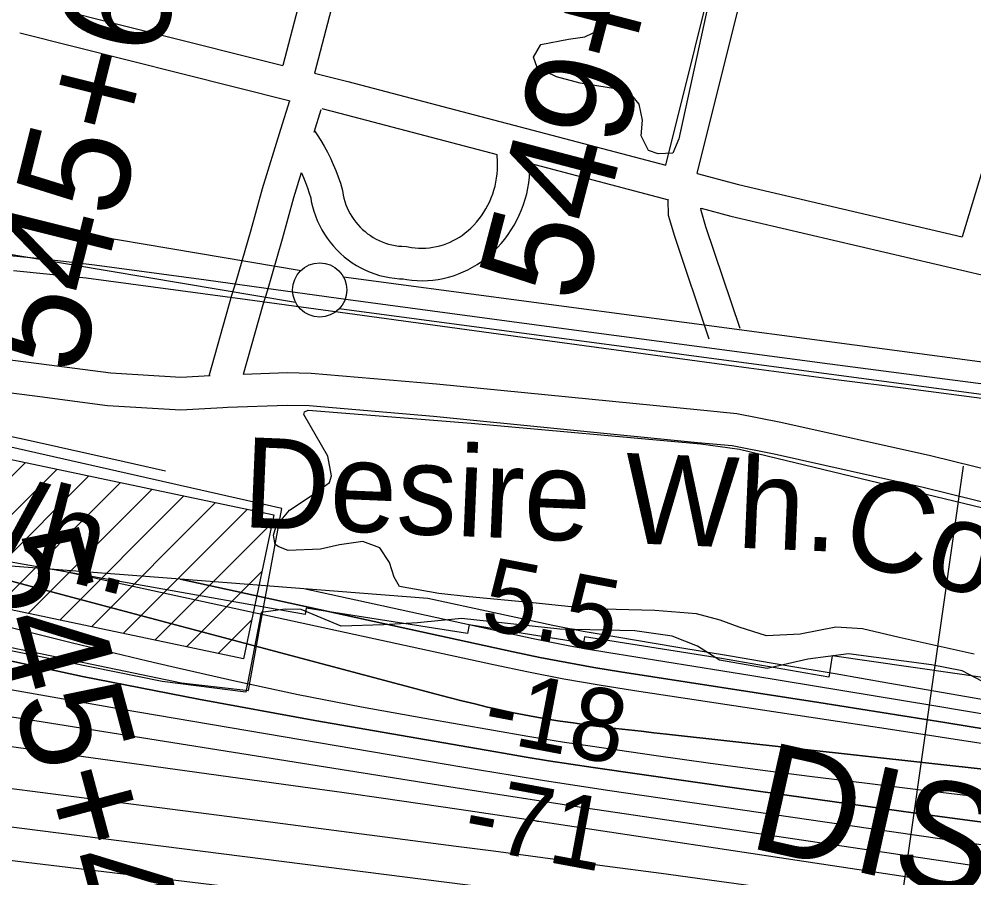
# Model space of a CAD drawing. Extents: x 3677843 to 3715951, y 511991 to 537744.
# Drawn here: x 3689113 to 3689993, y 533226 to 534017 of the extents above; entities that cross this region are included whole.
import ezdxf

# ---------------------------------------------------------------- set-up
doc = ezdxf.new("R2010")
doc.units = 0
for name, color, linetype in [('V-BLDG-IDEN', 7, 'Continuous'), ('V-BLDG-OTLN', 7, 'Continuous'), ('V-CHAN-DOCK', 7, 'Continuous'), ('V-RAIL-TRAK', 7, 'Continuous'), ('V-RIVR-EDGE', 7, 'Continuous'), ('V-RIVR-RANG', 7, 'Continuous'), ('V-ROAD-CNTR', 7, 'Continuous'), ('V-RRAP-RVMT', 7, 'Continuous'), ('V-RRAP-RVMT-IDEN', 7, 'Continuous'), ('V-SITE-VEGE', 7, 'Continuous'), ('V-SURV-IDEN', 7, 'Continuous'), ('V-SURV-LINE', 7, 'Continuous'), ('V-TOPO-DPTH', 7, 'Continuous'), ('V-TOPO-MAJR', 7, 'Continuous'), ('V-TOPO-MINR', 7, 'Continuous'), ('V-TOPO-WATR', 7, 'Continuous')]:
    doc.layers.add(name, color=color, linetype=linetype)

msp = doc.modelspace()

# ---------------------------------------------------------------- linework, layer by layer
at = {"layer": 'V-BLDG-OTLN'}
for p, q in [((3689004.53, 533494.26), (3689119.04, 533608.77)), ((3689033.73, 533488.11), (3689148.25, 533602.62)), ((3689062.94, 533481.95), (3689177.45, 533596.47)), ((3689092.14, 533475.8), (3689206.66, 533590.32)), ((3689121.35, 533469.65), (3689235.86, 533584.16)), ((3689150.55, 533463.5), (3689265.06, 533578.01)), ((3689179.76, 533457.35), (3689294.27, 533571.86)), ((3689208.96, 533451.2), (3689323.47, 533565.71)), ((3689238.16, 533445.05), (3689346.22, 533553.1)), ((3689267.37, 533438.9), (3689336.78, 533508.31)), ((3689296.57, 533432.74), (3689327.35, 533463.52))]:
    msp.add_line(p, q, dxfattribs=at)
msp.add_lwpolyline([(3688875.36, 533660.09), (3689347.79, 533560.59), (3689319.83, 533427.84), (3688828.91, 533531.25), (3688853.81, 533649.47), (3688872.31, 533645.58)], close=True, dxfattribs=at)
at = {"layer": 'V-CHAN-DOCK'}
for points in [[(3689334.93, 533456.71), (3689355.18, 533566.45), (3688859.4, 533678.6)], [(3689000.15, 533460.1), (3689143.16, 533430.64), (3689262.83, 533405.52), (3689324.55, 533398.53), (3689334.93, 533456.71)]]:
    msp.add_lwpolyline(points, dxfattribs=at)
at = {"layer": 'V-RAIL-TRAK'}
for points in [[(3687602.47, 533966), (3687663.49, 533948.65), (3687697.33, 533939.03), (3687747.16, 533923.87), (3687776.4, 533911.85), (3687837.18, 533889.99), (3687884.96, 533875.49), (3687949.07, 533861.83), (3688131.79, 533826.89), (3688277.03, 533798.37), (3688339.05, 533788.78), (3688360.19, 533784.9), (3688421.59, 533769.17), (3688503.39, 533755.01), (3688607.71, 533734.94), (3688724.29, 533714.31), (3688805.42, 533699.46), (3688857.27, 533686.36), (3688953.42, 533666.21), (3689033.23, 533647.95), (3689117.79, 533630.41), (3689209.86, 533609.54), (3689248.06, 533601.07)], [(3689094.69, 533800.45), (3689133.09, 533796.72), (3689182.48, 533791.04), (3689285.38, 533776.98), (3689327.58, 533771.22), (3689416.41, 533759.09), (3689624.28, 533731), (3689860.26, 533699.76), (3690088.7, 533669.81)], [(3691266.87, 533413.55), (3691105.3, 533454), (3691093.1, 533457.06), (3690844.48, 533519.01), (3690560.85, 533588.83), (3690529.95, 533596.06), (3690470.25, 533605.06), (3690353.64, 533620.35), (3690284.35, 533629.95), (3690166.11, 533645.88), (3689927.62, 533677.13), (3689868.63, 533684.77), (3689780.82, 533696.23), (3689583.93, 533723.06), (3689393.22, 533749.27), (3689323.58, 533758.65), (3689175.06, 533778.64), (3689107.85, 533785.51)]]:
    msp.add_lwpolyline(points, dxfattribs=at)
at = {"layer": 'V-RIVR-EDGE'}
msp.add_lwpolyline([(3690000.97, 533406.88), (3689982, 533416.73), (3689953.83, 533422.31), (3689877.27, 533432.31), (3689839.88, 533427.5), (3689802.48, 533419.01), (3689758.38, 533426.47), (3689738.2, 533439.39), (3689714.93, 533448.64), (3689680.63, 533453.62), (3689611.4, 533455.02), (3689520.74, 533465.05), (3689480.29, 533460.86), (3689449.04, 533459.1), (3689409.82, 533457.97), (3689373.09, 533473.38), (3689358.39, 533473.42), (3689336.32, 533470.41), (3689322.05, 533396.91), (3689244.87, 533406.91), (3689008.48, 533454.67)], dxfattribs=at)
at = {"layer": 'V-RIVR-RANG'}
msp.add_line((3689983.07, 533605.29), (3689864.68, 532773.68), dxfattribs=at)
at = {"layer": 'V-ROAD-CNTR'}
for points in [[(3689438.99, 534292.04), (3689356.17, 533974.83)], [(3689468.13, 534284.91), (3689385.27, 533967.54)], [(3689708.98, 533882.7), (3689789.7, 534206.15)], [(3689737.99, 533875.06), (3689818.84, 534199.02)], [(3690072.79, 534138.34), (3690034.22, 533989.01), (3689982.11, 533816.8)], [(3689114.62, 534035.4), (3689356.17, 533974.83)], [(3689113.67, 534004.72), (3689363.04, 533942.18)], [(3689385.27, 533967.54), (3689416.02, 533959.83), (3689708.98, 533882.7)], [(3689288.33, 533688.77), (3689309.21, 533762.95), (3689313.23, 533775.58), (3689326.97, 533823.07), (3689337.51, 533861.4), (3689354.35, 533916.14), (3689362.62, 533942.29)], [(3689384.93, 533913.32), (3689391.5, 533934.11)], [(3689392.05, 533934.91), (3689408.55, 533930.77), (3689553.81, 533892.53)], [(3689385.27, 533914.4), (3689387.79, 533910.77), (3689391.14, 533905.54), (3689394.3, 533900.19), (3689397.27, 533894.74), (3689400.05, 533889.19), (3689402.63, 533883.54), (3689405.01, 533877.8), (3689407.18, 533871.98), (3689409.15, 533866.09), (3689411.07, 533859.56), (3689411.82, 533855.29), (3689412.5, 533852.29), (3689413.34, 533849.32), (3689414.33, 533846.41), (3689415.48, 533843.55), (3689416.77, 533840.75), (3689418.21, 533838.03), (3689419.78, 533835.38), (3689421.5, 533832.82), (3689423.34, 533830.35), (3689425.31, 533827.99), (3689427.4, 533825.72), (3689429.61, 533823.57), (3689431.92, 533821.54), (3689434.33, 533819.63), (3689436.85, 533817.85), (3689439.45, 533816.21), (3689442.14, 533814.7), (3689444.9, 533813.34), (3689447.73, 533812.11), (3689450.62, 533811.04), (3689453.56, 533810.13), (3689456.55, 533809.36), (3689459.56, 533808.75), (3689462.61, 533808.31), (3689465.68, 533808.02), (3689470.14, 533807.83), (3689474.75, 533807.02), (3689478.02, 533806.62), (3689481.31, 533806.39), (3689484.61, 533806.32), (3689487.91, 533806.43), (3689491.2, 533806.7), (3689494.47, 533807.14), (3689497.71, 533807.75), (3689500.92, 533808.53), (3689504.08, 533809.46), (3689507.19, 533810.56), (3689510.25, 533811.82), (3689513.23, 533813.23), (3689516.14, 533814.8), (3689518.96, 533816.51), (3689521.69, 533818.36), (3689524.32, 533820.34), (3689526.85, 533822.47), (3689529.33, 533824.78), (3689532.03, 533827.5), (3689534.56, 533830.31), (3689536.97, 533833.23), (3689539.22, 533836.26), (3689541.34, 533839.39), (3689543.3, 533842.61), (3689545.11, 533845.93), (3689546.76, 533849.33), (3689548.25, 533852.8), (3689549.57, 533856.34), (3689550.73, 533859.93), (3689551.71, 533863.58), (3689552.53, 533867.28), (3689553.16, 533870.99), (3689553.63, 533874.74), (3689553.91, 533878.51), (3689554.02, 533882.29), (3689553.95, 533886.06), (3689553.55, 533892.18)], [(3689373.27, 533875.61), (3689375.12, 533871.56), (3689377.09, 533866.8), (3689378.89, 533861.98), (3689380.53, 533857.09), (3689381.81, 533852.73), (3689382.39, 533849.39), (3689383.42, 533844.86), (3689384.69, 533840.39), (3689386.19, 533835.99), (3689387.92, 533831.68), (3689389.87, 533827.46), (3689392.03, 533823.35), (3689394.41, 533819.35), (3689396.99, 533815.49), (3689399.77, 533811.77), (3689402.75, 533808.19), (3689405.9, 533804.78), (3689409.22, 533801.54), (3689412.72, 533798.48), (3689416.37, 533795.6), (3689420.16, 533792.91), (3689424.09, 533790.43), (3689428.14, 533788.15), (3689432.31, 533786.1), (3689436.57, 533784.26), (3689440.93, 533782.64), (3689445.37, 533781.26), (3689449.86, 533780.1), (3689454.42, 533779.19), (3689459.02, 533778.51), (3689463.65, 533778.08), (3689466.91, 533777.94), (3689470.32, 533777.34), (3689475.13, 533776.75), (3689479.95, 533776.41), (3689484.79, 533776.31), (3689489.63, 533776.47), (3689494.45, 533776.87), (3689499.24, 533777.51), (3689504, 533778.41), (3689508.71, 533779.54), (3689513.35, 533780.92), (3689517.91, 533782.53), (3689522.38, 533784.38), (3689526.76, 533786.44), (3689531.02, 533788.74), (3689535.16, 533791.24), (3689539.17, 533793.96), (3689543.03, 533796.88), (3689546.74, 533799.99), (3689550.21, 533803.23), (3689553.83, 533806.87), (3689557.3, 533810.72), (3689560.6, 533814.73), (3689563.7, 533818.89), (3689566.6, 533823.2), (3689569.3, 533827.64), (3689571.78, 533832.19), (3689574.05, 533836.85), (3689576.1, 533841.62), (3689577.91, 533846.48), (3689579.5, 533851.43), (3689580.86, 533856.44), (3689581.97, 533861.5), (3689582.85, 533866.62), (3689583.49, 533871.77), (3689583.88, 533876.94), (3689584.03, 533882.13), (3689583.98, 533884.58)], [(3689583.79, 533884.63), (3689711.67, 533850.97)], [(3689319.9, 533690.22), (3689337.95, 533754.34), (3689341.94, 533766.86), (3689355.84, 533814.92), (3689366.32, 533853.01), (3689373.38, 533875.97)], [(3689737.99, 533875.06), (3689776.07, 533865.03), (3689982.11, 533816.8)], [(3689749.12, 533722.57), (3689717.26, 533817.1), (3689711.68, 533836.29), (3689711.19, 533851.09)], [(3689777.55, 533732.15), (3689745.89, 533826.08), (3689741.54, 533841.05), (3689741.47, 533843.12)], [(3689741.64, 533843.08), (3689768.83, 533835.92), (3690100.22, 533758.34), (3690612.35, 533625.64), (3690894.5, 533559.6), (3691159.97, 533495.29), (3691208.29, 533482.58)], [(3688471.3, 533802.39), (3688711.98, 533762.57), (3688967.48, 533722.91), (3689042.25, 533711.43), (3689131.36, 533700.08), (3689197.66, 533691.28), (3689262.29, 533687.26), (3689289.14, 533688.82)], [(3689319.56, 533690.21), (3689360.12, 533691.6), (3689382.12, 533691.11), (3689497.8, 533681.31), (3689741.06, 533657.16), (3689774.46, 533654.01), (3689814.93, 533646.05), (3689953.05, 533615.35), (3690239.69, 533544.65)], [(3689038.08, 533681.72), (3689127.49, 533670.33), (3689194.75, 533661.4), (3689262.23, 533657.2), (3689300.74, 533659.45), (3689305.12, 533659.7), (3689360.3, 533661.59), (3689380.51, 533661.14), (3689495.05, 533651.43), (3689738.17, 533627.3), (3689770.15, 533624.29), (3689808.78, 533616.69), (3689946.2, 533586.14), (3690232.6, 533515.5)]]:
    msp.add_lwpolyline(points, dxfattribs=at)
at = {"layer": 'V-RRAP-RVMT'}
for points in [[(3689633.24, 533442.27), (3689527.85, 533459.14), (3689526.41, 533451.28), (3689377.6, 533474.35), (3689376.67, 533468.5), (3689094.94, 533518.68), (3689100.33, 533550.74), (3688954.27, 533578.27), (3688957.13, 533598.79), (3688817.32, 533626.57), (3688817.78, 533630.14), (3688670.66, 533660.32), (3688670.54, 533659.68), (3688553.23, 533683.31), (3688528.78, 533553.69)], [(3690009.36, 533409.37), (3689862.36, 533430.69), (3689859.34, 533410.9), (3689760.48, 533427.97), (3689760.51, 533428.16), (3689634.21, 533447.97), (3689633.24, 533442.27)]]:
    msp.add_lwpolyline(points, dxfattribs=at)
at = {"layer": 'V-SITE-VEGE'}
msp.add_lwpolyline([(3689759.98, 534085.99), (3689720.99, 533906.95), (3689715.68, 533893.99), (3689702.1, 533893.18), (3689693.24, 533896.49), (3689686.31, 533910.01), (3689687.53, 533924.28), (3689684.66, 533939.2), (3689677.79, 533947.28), (3689662.79, 533953.25), (3689630.13, 533958.36), (3689608.34, 533964.26), (3689590.59, 533972.92), (3689587.1, 533982.39), (3689593.78, 533994.01), (3689619.54, 533999.02), (3689634.46, 534001.2), (3689647.99, 534007.45), (3689662.67, 534034.09), (3689675.08, 534085.16), (3689677.66, 534098.09), (3689691.2, 534103.66), (3689723.85, 534098.54)], close=True, dxfattribs=at)
msp.add_lwpolyline([(3689993.13, 533431.98), (3689924.06, 533447.51), (3689890.21, 533455.29), (3689865.87, 533457.07), (3689832.83, 533450.67), (3689801.76, 533449.01), (3689776.69, 533456.87), (3689759.06, 533463.45), (3689737.38, 533469.32), (3689698.84, 533472.31), (3689639.38, 533473.75), (3689586.63, 533479.31), (3689527.79, 533484.82), (3689500.06, 533487.92), (3689463.52, 533494.32), (3689458.7, 533503.05), (3689454.52, 533516.52), (3689445.6, 533529.95), (3689430, 533535.87), (3689408.41, 533532.96), (3689390.89, 533528.73), (3689361.17, 533527.76), (3689352.36, 533531.05), (3689348.96, 533533.05), (3689347.52, 533541.81), (3689350.15, 533549.95), (3689362.16, 533564.93), (3689382.3, 533577.96), (3689399.07, 533590.29), (3689401.03, 533596.39), (3689397.48, 533614.59), (3689375.48, 533652.89), (3689376.13, 533655.6), (3689379.49, 533656.98), (3689529.59, 533644.95), (3689741.24, 533626.09), (3689777.1, 533621.04), (3690121.12, 533537.96)], dxfattribs=at)
at = {"layer": 'V-SURV-LINE'}
for points in [[(3689059.73, 533838.43), (3689372.93, 533785.88)], [(3689367.98, 533756.29), (3689056.89, 533808.48)], [(3689411.94, 533780.01), (3690353.79, 533654.5)], [(3690349.84, 533624.76), (3689407.99, 533750.27)]]:
    msp.add_lwpolyline(points, dxfattribs=at)
msp.add_circle((3689390.15, 533767.78), 25, dxfattribs=at)
at = {"layer": 'V-TOPO-DPTH'}
for points in [[(3689032.99, 533518.64), (3689497.32, 533395.2), (3689509.17, 533392.11), (3689521.05, 533389.09), (3689532.95, 533386.17), (3689544.86, 533383.33), (3689549.4, 533382.27), (3689559.08, 533380.1), (3689568.78, 533378.04), (3689578.52, 533376.15), (3689588.27, 533374.37), (3689604.07, 533371.63), (3689605.95, 533371.32), (3689607.82, 533371.01), (3689609.7, 533370.72), (3689611.58, 533370.44), (3689623.8, 533368.68), (3689631.79, 533367.56), (3689639.79, 533366.48), (3689647.79, 533365.47), (3689655.81, 533364.51), (3689663.07, 533363.66), (3689674.72, 533362.32), (3689686.38, 533360.99), (3689698.03, 533359.67), (3689709.69, 533358.37), (3690070.87, 533318.34)], [(3693858.12, 532595.84), (3691015.63, 533179.63), (3690973.58, 533188.25), (3690931.52, 533196.84), (3690889.46, 533205.39), (3690847.39, 533213.92), (3690821.55, 533219.14), (3690792.38, 533224.93), (3690763.19, 533230.58), (3690733.95, 533236.01), (3690704.68, 533241.29), (3690314.1, 533310.37), (3690198.23, 533330.48), (3690082.29, 533350.11), (3689966.23, 533369.01), (3689850.08, 533387.43), (3689667.42, 533415.8), (3689642.59, 533419.89), (3689617.81, 533424.28), (3689593.12, 533429.11), (3689568.48, 533434.24), (3689261.44, 533501.09), (3689032.99, 533518.64)], [(3689032.99, 533518.64), (3689497.32, 533395.2), (3689509.17, 533392.11), (3689521.05, 533389.09), (3689532.95, 533386.17), (3689544.86, 533383.33), (3689549.4, 533382.27), (3689559.08, 533380.1), (3689568.78, 533378.04), (3689578.52, 533376.15), (3689588.27, 533374.37), (3689604.07, 533371.63), (3689605.95, 533371.32), (3689607.82, 533371.01), (3689609.7, 533370.72), (3689611.58, 533370.44), (3689623.8, 533368.68), (3689631.79, 533367.56), (3689639.79, 533366.48), (3689647.79, 533365.47), (3689655.81, 533364.51), (3689663.07, 533363.66), (3689674.72, 533362.32), (3689686.38, 533360.99), (3689698.03, 533359.67), (3689709.69, 533358.37), (3690070.87, 533318.34)], [(3694353.57, 532541.82), (3690852.21, 533240.67), (3690838.27, 533243.43), (3690824.32, 533246.16), (3690810.37, 533248.86), (3690796.41, 533251.52), (3690782.44, 533254.13), (3690768.46, 533256.7), (3690754.47, 533259.21), (3690740.48, 533261.68), (3689913.5, 533405.47), (3689865.19, 533413.82), (3689816.87, 533422.09), (3689768.53, 533430.26), (3689720.19, 533438.36), (3689642.09, 533451.36), (3689632.8, 533452.97), (3689623.51, 533454.68), (3689614.26, 533456.53), (3689605.02, 533458.47), (3689489.88, 533483.54), (3689261.44, 533501.09)], [(3689261.44, 533501.09), (3689568.48, 533434.24), (3689593.12, 533429.11), (3689617.81, 533424.28), (3689642.59, 533419.89), (3689667.42, 533415.8), (3689850.08, 533387.43), (3689966.23, 533369.01), (3690082.29, 533350.11), (3690198.23, 533330.48), (3690314.1, 533310.37), (3690704.68, 533241.29), (3690733.95, 533236.01), (3690763.19, 533230.58), (3690792.38, 533224.93), (3690821.55, 533219.14), (3690847.39, 533213.92), (3690889.46, 533205.39), (3690931.52, 533196.84), (3690973.58, 533188.25), (3691015.63, 533179.63), (3693858.12, 532595.84)], [(3690021.85, 533297.45), (3689946.55, 533306.48), (3689892.08, 533313.05), (3689844.04, 533319.01), (3689796.04, 533325.2), (3689748.07, 533331.72), (3689700.14, 533338.47), (3689626.89, 533349.04), (3689615.61, 533350.72), (3689604.34, 533352.46), (3689593.09, 533354.3), (3689581.84, 533356.2), (3689487.05, 533372.64), (3689428.52, 533383.33), (3689370.14, 533394.72), (3689311.97, 533407.17), (3689253.94, 533420.31), (3689231.43, 533425.62), (3689162.34, 533442.27), (3689093.37, 533459.37)], [(3690021.85, 533297.45), (3689946.55, 533306.48), (3689892.08, 533313.05), (3689844.04, 533319.01), (3689796.04, 533325.2), (3689748.07, 533331.72), (3689700.14, 533338.47), (3689626.89, 533349.04), (3689615.61, 533350.72), (3689604.34, 533352.46), (3689593.09, 533354.3), (3689581.84, 533356.2), (3689487.05, 533372.64), (3689428.52, 533383.33), (3689370.14, 533394.72), (3689311.97, 533407.17), (3689253.94, 533420.31), (3689231.43, 533425.62), (3689162.34, 533442.27), (3689093.37, 533459.37)], [(3689064.86, 533434.5), (3689171.48, 533411.53), (3689278.5, 533390.55), (3689385.8, 533370.91), (3689559.61, 533340.76), (3689580.23, 533337.28), (3689600.86, 533333.91), (3689621.52, 533330.72), (3689642.2, 533327.64), (3689776.5, 533308.25), (3689864.38, 533295.82), (3689952.31, 533283.72), (3690040.3, 533272.12)], [(3689064.86, 533434.5), (3689171.48, 533411.53), (3689278.5, 533390.55), (3689385.8, 533370.91), (3689559.61, 533340.76), (3689580.23, 533337.28), (3689600.86, 533333.91), (3689621.52, 533330.72), (3689642.2, 533327.64), (3689776.5, 533308.25), (3689864.38, 533295.82), (3689952.31, 533283.72), (3690040.3, 533272.12)]]:
    msp.add_lwpolyline(points, dxfattribs=at)
at = {"layer": 'V-TOPO-MAJR'}
for points in [[(3690114.12, 533239.54), (3689984.92, 533258.42), (3689855.72, 533277.28), (3689657.5, 533306.16), (3689627.42, 533310.66), (3689597.37, 533315.29), (3689567.34, 533320.14), (3689537.34, 533325.13), (3689208.25, 533381.09), (3689078.87, 533403.67)], [(3690174.93, 533097.37), (3689577.44, 533182.29), (3689575, 533182.64), (3689572.57, 533182.98), (3689570.13, 533183.31), (3689567.69, 533183.64), (3689483.77, 533194.89), (3689439.36, 533200.75), (3689394.94, 533206.49), (3689350.49, 533212.06), (3689306.03, 533217.51), (3688465.86, 533318.77)]]:
    msp.add_lwpolyline(points, dxfattribs=at)
at = {"layer": 'V-TOPO-MINR'}
for points in [[(3690070.87, 533318.34), (3689709.69, 533358.37), (3689698.03, 533359.67), (3689686.38, 533360.99), (3689674.72, 533362.32), (3689663.07, 533363.66), (3689655.81, 533364.51), (3689647.79, 533365.47), (3689639.79, 533366.48), (3689631.79, 533367.56), (3689623.8, 533368.68), (3689611.58, 533370.44), (3689609.7, 533370.72), (3689607.82, 533371.01), (3689605.95, 533371.32), (3689604.07, 533371.63), (3689588.27, 533374.37), (3689578.52, 533376.15), (3689568.78, 533378.04), (3689559.08, 533380.1), (3689549.4, 533382.27), (3689544.86, 533383.33), (3689532.95, 533386.17), (3689521.05, 533389.09), (3689509.17, 533392.11), (3689497.32, 533395.2), (3689032.99, 533518.64)], [(3693620.55, 532622.15), (3691098.27, 533148.46), (3691042.03, 533160.21), (3690985.79, 533171.96), (3690929.55, 533183.73), (3690873.32, 533195.5), (3690807.23, 533209.35), (3690784.02, 533214.11), (3690760.79, 533218.74), (3690737.52, 533223.17), (3690714.22, 533227.47), (3690479.73, 533269.69), (3690339.07, 533294.39), (3690198.27, 533318.27), (3690057.28, 533340.93), (3689916.14, 533362.77), (3689680.11, 533398.25), (3689647.5, 533403.48), (3689614.97, 533409.13), (3689582.55, 533415.42), (3689550.21, 533422.13), (3689147.21, 533509.87)], [(3693858.12, 532595.84), (3691015.63, 533179.63), (3690973.58, 533188.25), (3690931.52, 533196.84), (3690889.46, 533205.39), (3690847.39, 533213.92), (3690821.55, 533219.14), (3690792.38, 533224.93), (3690763.19, 533230.58), (3690733.95, 533236.01), (3690704.68, 533241.29), (3690314.1, 533310.37), (3690198.23, 533330.48), (3690082.29, 533350.11), (3689966.23, 533369.01), (3689850.08, 533387.43), (3689667.42, 533415.8), (3689642.59, 533419.89), (3689617.81, 533424.28), (3689593.12, 533429.11), (3689568.48, 533434.24), (3689261.44, 533501.09)], [(3694102.55, 532569.06), (3690933.62, 533210.35), (3690905.67, 533215.98), (3690877.71, 533221.57), (3690849.74, 533227.1), (3690821.77, 533232.6), (3690793.77, 533237.99), (3690765.75, 533243.26), (3690737.7, 533248.37), (3690709.63, 533253.36), (3690123.6, 533355.8), (3690039.86, 533370.26), (3689956.08, 533384.49), (3689872.25, 533398.38), (3689788.38, 533412.03), (3689654.74, 533433.5), (3689637.68, 533436.39), (3689620.66, 533439.46), (3689603.69, 533442.82), (3689586.76, 533446.36), (3689375.66, 533492.32)], [(3690021.85, 533297.45), (3689946.55, 533306.48), (3689892.08, 533313.05), (3689844.04, 533319.01), (3689796.04, 533325.2), (3689748.07, 533331.72), (3689700.14, 533338.47), (3689626.89, 533349.04), (3689615.61, 533350.72), (3689604.34, 533352.46), (3689593.09, 533354.3), (3689581.84, 533356.2), (3689487.05, 533372.64), (3689428.52, 533383.33), (3689370.14, 533394.72), (3689311.97, 533407.17), (3689253.94, 533420.31), (3689231.43, 533425.62), (3689162.34, 533442.27), (3689093.37, 533459.37)], [(3691471.62, 532897.59), (3690754.91, 533089.04), (3690745.23, 533091.51), (3690735.53, 533093.85), (3690725.78, 533095.97), (3690715.99, 533097.94), (3690600.28, 533120.04), (3690532.55, 533132.57), (3690464.73, 533144.57), (3690396.78, 533155.78), (3690328.74, 533166.47), (3689592.05, 533277.83), (3689591.22, 533277.95), (3689590.4, 533278.08), (3689589.57, 533278.2), (3689588.75, 533278.33), (3689518.54, 533288.88), (3689482.6, 533294.22), (3689446.65, 533299.47), (3689410.68, 533304.59), (3689374.7, 533309.62), (3688497.35, 533430.71)], [(3691492.02, 532923.84), (3691414.25, 532944.14), (3691336.49, 532964.47), (3691258.69, 532984.63), (3691180.82, 533004.52), (3691102.9, 533024.25), (3690780.36, 533105.33), (3690760.09, 533110.18), (3690739.75, 533114.72), (3690719.32, 533118.81), (3690698.82, 533122.58), (3690512.74, 533154.66), (3690399.08, 533173.83), (3690285.34, 533192.47), (3690171.47, 533210.3), (3690057.51, 533227.59), (3689672.78, 533284.56), (3689633.3, 533290.47), (3689593.84, 533296.47), (3689554.4, 533302.61), (3689514.97, 533308.83), (3688739.99, 533432.49)], [(3690040.3, 533272.12), (3689952.31, 533283.72), (3689864.38, 533295.82), (3689776.5, 533308.25), (3689642.2, 533327.64), (3689621.52, 533330.72), (3689600.86, 533333.91), (3689580.23, 533337.28), (3689559.61, 533340.76), (3689385.8, 533370.91), (3689278.5, 533390.55), (3689171.48, 533411.53), (3689064.86, 533434.5)], [(3691519.23, 532824.96), (3690772.87, 533014.95), (3690747.48, 533021.14), (3690722.01, 533026.97), (3690696.42, 533032.27), (3690670.75, 533037.22), (3690341.75, 533097.12), (3690214.94, 533119.32), (3690087.96, 533140.36), (3689960.7, 533159.68), (3689833.25, 533177.85), (3689612.68, 533207.77), (3689595.38, 533210.09), (3689578.08, 533212.38), (3689560.78, 533214.64), (3689543.47, 533216.86), (3688646.23, 533330.89)], [(3690317.47, 533143.89), (3689945.3, 533196.6), (3689885.18, 533205.05), (3689825.04, 533213.42), (3689764.89, 533221.65), (3689704.73, 533229.8), (3689652.77, 533236.79), (3689618.57, 533241.36), (3689584.37, 533245.9), (3689550.16, 533250.4), (3689515.94, 533254.87), (3689297.48, 533283.26), (3689154.03, 533301.85), (3689010.57, 533320.37)]]:
    msp.add_lwpolyline(points, dxfattribs=at)
at = {"layer": 'V-TOPO-WATR'}
msp.add_lwpolyline([(3694353.57, 532541.82), (3690852.21, 533240.67), (3690838.27, 533243.43), (3690824.32, 533246.16), (3690810.37, 533248.86), (3690796.41, 533251.52), (3690782.44, 533254.13), (3690768.46, 533256.7), (3690754.47, 533259.21), (3690740.48, 533261.68), (3689913.5, 533405.47), (3689865.19, 533413.82), (3689816.87, 533422.09), (3689768.53, 533430.26), (3689720.19, 533438.36), (3689642.09, 533451.36), (3689632.8, 533452.97), (3689623.51, 533454.68), (3689614.26, 533456.53), (3689605.02, 533458.47), (3689489.88, 533483.54)], dxfattribs=at)

# ---------------------------------------------------------------- texts
at = {"layer": 'V-BLDG-IDEN'}
for s, height, rotation, p in [('Piety Wh.', 83, 345.71277, (3688752.23, 533602.35)), ('Desire Wh.', 83, 357.61414, (3689318.1, 533549.28)), ('Congress St. Wh.', 82.9998, 344.61154, (3689867.07, 533520.27))]:
    msp.add_text(s, height=height, rotation=rotation, dxfattribs=at).set_placement(p)
at = {"layer": 'V-RIVR-RANG'}
for s, rotation, p in [('5.5', 349.23833, (3689536.73, 533456.06)), ('-18', 349.23833, (3689538.26, 533353.98)), ('-71', 349.52056, (3689520.19, 533255.3))]:
    msp.add_text(s, height=67, rotation=rotation, dxfattribs=at).set_placement(p)
at = {"layer": 'V-RRAP-RVMT-IDEN'}
msp.add_text('DISTRICT', height=100, rotation=347.4141, dxfattribs=at).set_placement((3689783.01, 533254.38))
at = {"layer": 'V-SURV-IDEN'}
for s, rotation, p in [('   549+25.9   ', 75.35746, (3689603.36, 533645.19)), ('   545+68.4   ', 75.91823, (3689141.87, 533578.93)), ('   545+48.9  ', 284.9559, (3689040, 533641.82))]:
    msp.add_text(s, height=100, rotation=rotation, dxfattribs=at).set_placement(p)

doc.saveas('drawing.dxf')
